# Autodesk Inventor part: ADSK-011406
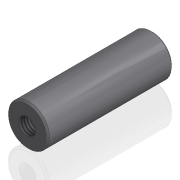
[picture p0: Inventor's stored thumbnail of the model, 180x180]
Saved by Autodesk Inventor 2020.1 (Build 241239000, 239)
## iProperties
Created: 2000-01
Part Number: ADSK-011406
Material: Acier doux
Document SubType Name: Modeling
Designer: glanglot
Density: 7.86 g/cm^3
Appearance: Metal-Steel(Polish)
Mass: 250.622 g
Surface Area: 89.3387 cm^2
Volume: 31.8858 cm^3
Control State: 0
Checked Out: False
Master: False
Shininess: 0.0
Length Units: 11269
Angle Units: 11279
Time Units: 11290
Mass Units: 11283
Length Display Precision: 3
Angle Display Precision: 2
Compacted: True
Material Desc: ROUND,CD 1018,1.0000 DIA
Material_Number: A084576
Cutlength: 3.06
Dimensions: 25x25x76 mm
Mass: 0,251 kg
Density: 0.0
Volumn: 0.0
Area: 0.0
PropertySet Name: Model Information
Author: glanglot
Revision Number: -
Title: ADSK-011406
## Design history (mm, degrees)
node "Extrusion1" dims "d1" = 76, "d2" = 0
  sketch "Sketch1"
    geometry: C1 r 12.5 at (0, 0); 1 further point
    constraints: 1 centre point, 1 coincident
    dimensions: "d0" = 25 diameter of C1
node "Hole1" dims "d3" = 10.106, "d4" = 9.525, "d5" = 6.35, "d6" = 60 deg, "d7" = 32.3, "d8" = 118 deg, "d13" = 24
node "Chamfer1" dims "d10" = 1, "d11" = 1, "d12" = 45 deg
node "Mirror1"
node "Solide1"
node "Corps solides"
node "Corps surfaciques"
sketch "Sketch2"
  geometry: C1 r 12.5 at (0, 0) reference
